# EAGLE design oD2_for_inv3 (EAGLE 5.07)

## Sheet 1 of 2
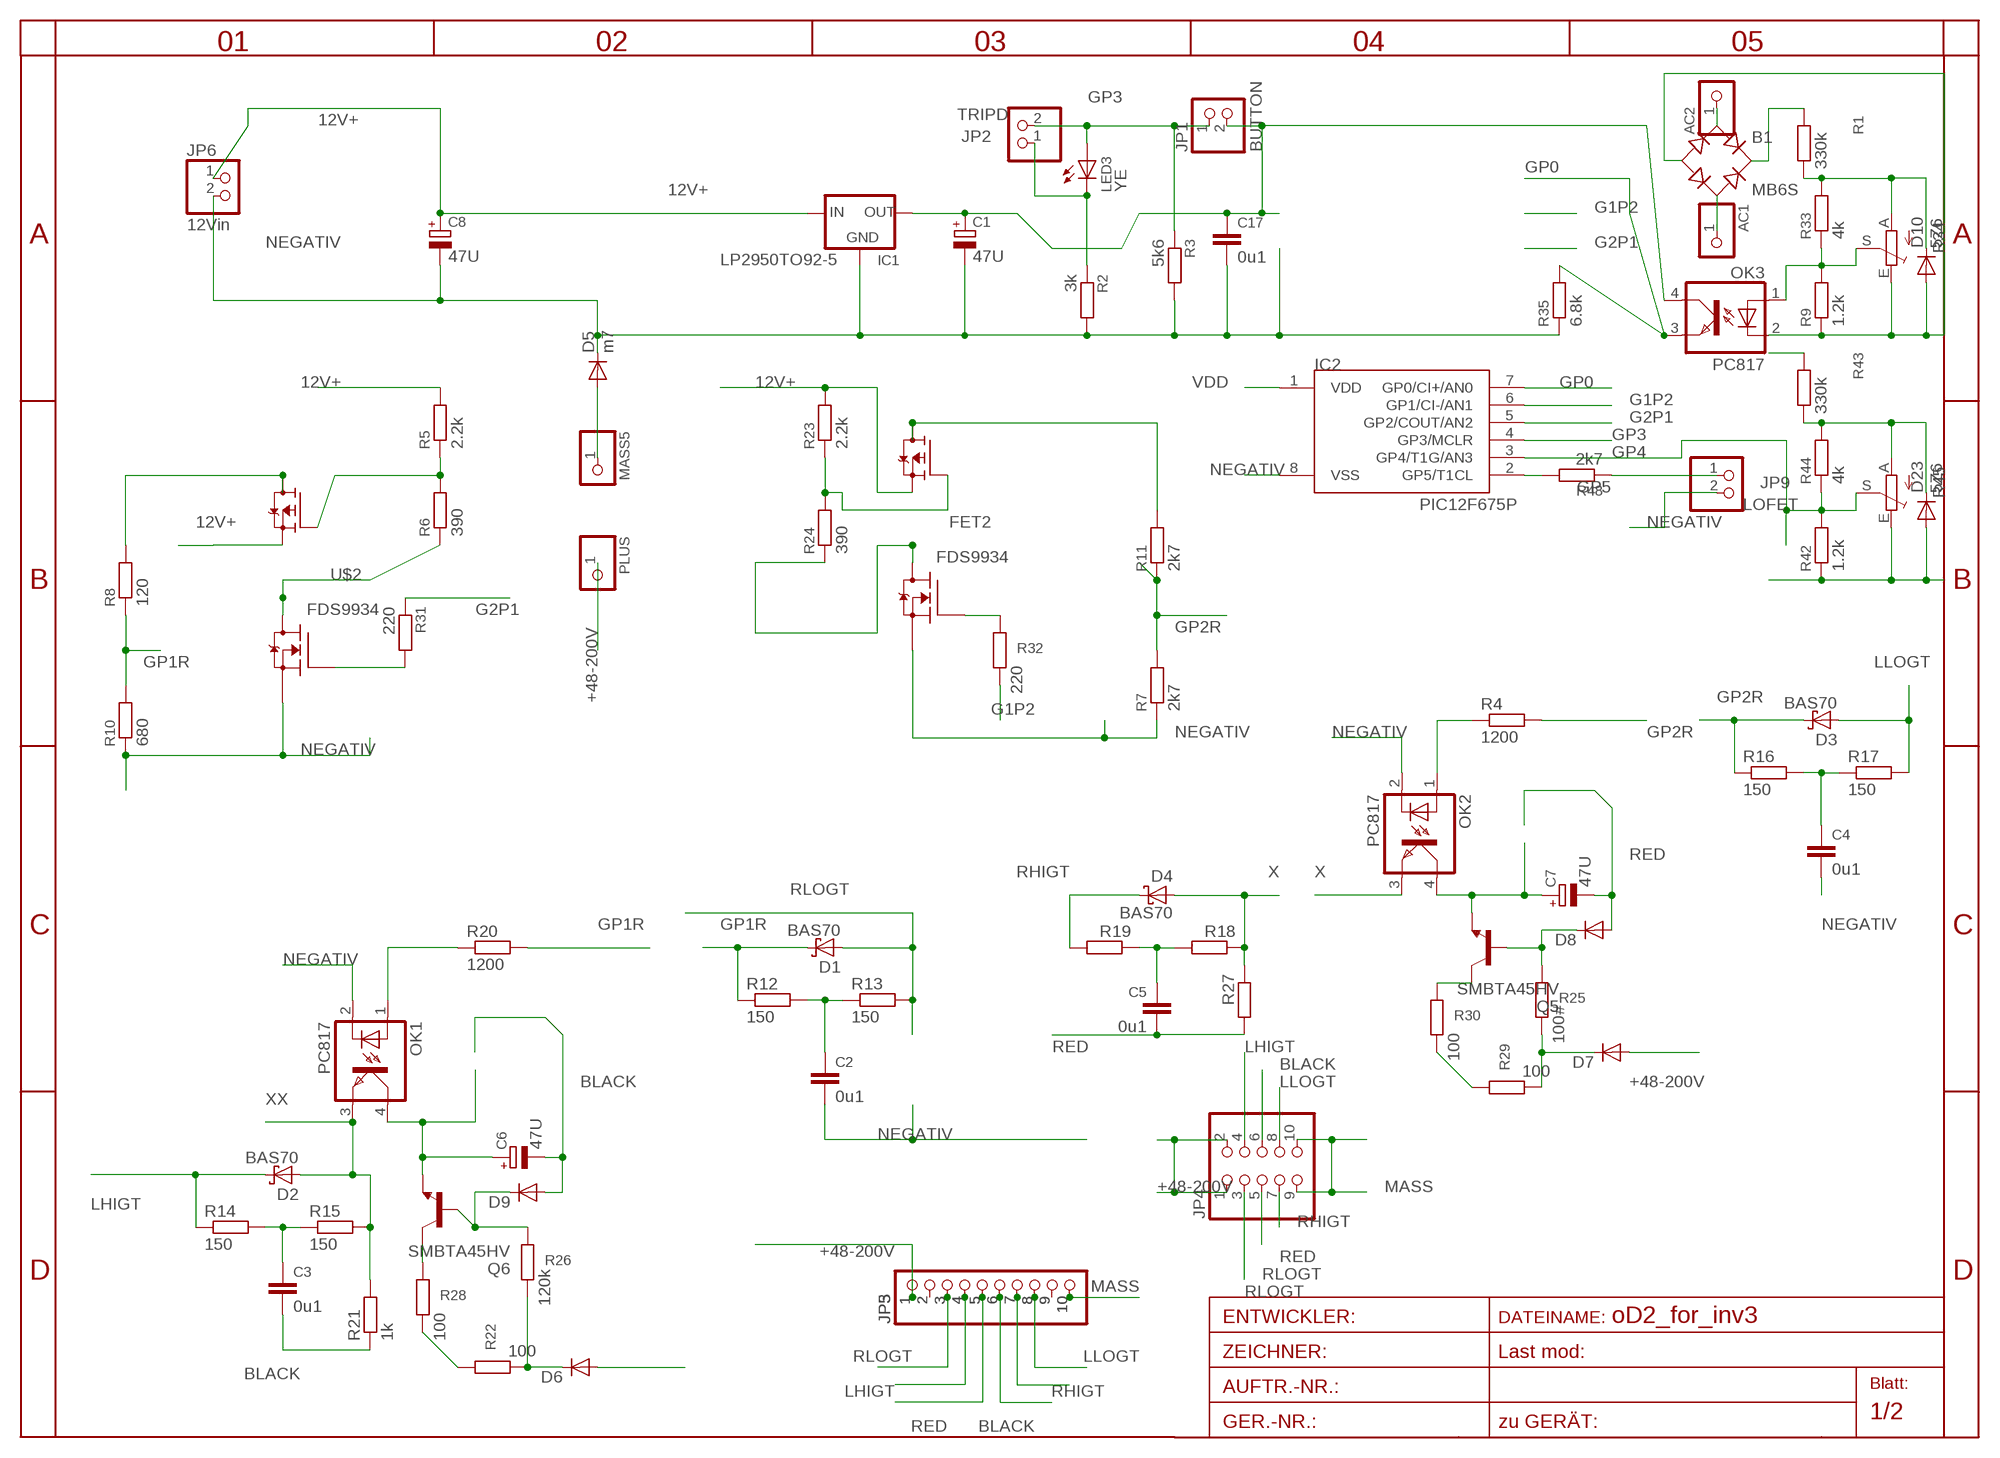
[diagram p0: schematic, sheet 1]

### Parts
AC1  PINHD-1X11MM6  [1X1MM8]
AC2  PINHD-1X11MM6  [1X1MM8]
B1  MB6S  [SOIC-4]
C1  47U  CPOL-EUE2.5-5  [E2,5-5]
C2  0u1  C-EUC1206  [C1206]
C3  0u1  C-EUC0805  [C0805]
C4  0u1  C-EUC1206  [C1206]
C5  0u1  C-EUC0805  [C0805]
C6  47U  CPOL-EUE2.5-6  [E2,5-6]
C7  47U  CPOL-EUE2.5-6  [E2,5-6]
C8  47U  CPOL-EUE2.5-7  [E2,5-7]
C17  0u1  C-EUC1206  [C1206]
D1  BAS70  [SOT23]
D2  BAS70  [SOT23]
D3  BAS70  [SOT23]
D4  BAS70  [SOT23]
D5  m7  DIODE-SMA-DO214  [SMA-DO214AC]
D6  DIODE-SMA-DO214  [SMA-DO214AC]
D7  DIODE-SMA-DO214  [SMA-DO214AC]
D8  DIODE-MINIMELF  [MINIMELF]
D9  DIODE-MINIMELF  [MINIMELF]
D10  5Z6  DIODE-MINIMELF  [MINIMELF]
D23  5Z6  DIODE-MINIMELF  [MINIMELF]
FET2  FDS9934  [SO-8]
IC1  LP2950TO92-5  [T092-5]
IC2  PIC12F675P  [DIL8]
JP1  BUTTON  PINHD-1X2STR  [1X02]
JP2  TRIPD  PINHD-1X2STR  [1X02]
JP3  PINHD-1X10  [1X10WIDE]
JP4  PINHD-2X5  [2X05]
JP5  PINHD-1X10  [1X10WIDE]
JP6  12Vin  PINHD-1X2STR  [1X02]
JP9  LOFET  PINHD-1X2STR  [1X02]
LED3  YE  LEDCHIPLED_1206  [CHIPLED_1206]
MASS5  PINHD-1X11MM6  [1X1MM8]
OK1  PC817  [DIL04]
OK2  PC817  [DIL04]
OK3  PC817  [DIL04]
PLUS  PINHD-1X11MM6  [1X1MM8]
Q5  SMBTA45HV  [SOT23HV]
Q6  SMBTA45HV  [SOT23HV]
R1  330k  R-EU_0204/5  [0204/5]
R2  3k  R-EU_R0805  [R0805]
R3  5k6  R-EU_R0805  [R0805]
R4  1200  R-EU_0204/7  [0204/7]
R5  2.2k  R-EU_R0805  [R0805]
R6  390  R-EU_R0805  [R0805]
R7  2k7  R-EU_R0805  [R0805]
R8  120  R-EU_R0805  [R0805]
R9  1.2k  R-EU_R0805  [R0805]
R10  680  R-EU_R0805  [R0805]
R11  2k7  R-EU_R0805  [R0805]
R12  150  R-EU_R0805  [R0805]
R13  150  R-EU_R0805  [R0805]
R14  150  R-EU_R0805  [R0805]
R15  150  R-EU_R0805  [R0805]
R16  150  R-EU_R0805  [R0805]
R17  150  R-EU_R0805  [R0805]
R18  R-EU_R0805  [R0805]
R19  R-EU_R0805  [R0805]
R20  1200  R-EU_0617/17  [0617/17]
R21  1k  R-EU_R0805  [R0805]
R22  100  R-EU_R1206  [R1206]
R23  2.2k  R-EU_R0805  [R0805]
R24  390  R-EU_R0805  [R0805]
R25  100#  R-EU_R1206  [R1206]
R26  120k  R-EU_R1206  [R1206]
R27  R-EU_R0805  [R0805]
R28  100  R-EU_R1206  [R1206]
R29  100  R-EU_R1206  [R1206]
R30  100  R-EU_R1206  [R1206]
R31  220  R-EU_R1206  [R1206]
R32  220  R-EU_R1206  [R1206]
R33  4k  R-EU_R0805  [R0805]
R34  TRIM_EU-S64W  [S64W]
R35  6.8k  R-EU_R0805  [R0805]
R42  1.2k  R-EU_R0805  [R0805]
R43  330k  R-EU_0207/50  [0207/50]
R44  4k  R-EU_R0805  [R0805]
R45  TRIM_EU-S64W  [S64W]
R48  2k7  R-EU_R0805  [R0805]
U$2  FDS9934  [SO-8]

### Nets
12V+: C8.+ FET2.3(Q2S) IC1.3(IN) JP6.1 R5.2 R23.2 U$2.3(Q2S)
+48-200V: D6.A D7.A JP3.1 JP4.1 JP4.2 JP5.1 PLUS.1 R43.2
BLACK: C3.2 C6.- D9.A JP3.6 JP4.6 JP5.6 R21.1
G1P2: IC2.6(GP1/CI-/AN1) R32.1
G2P1: IC2.5(GP2/COUT/AN2) R31.1
GP0: IC2.7(GP0/CI+/AN0) OK3.3(EMIT) R35.2
GP1R: D1.3(C) R8.1 R10.2 R12.1 R20.2
GP2R: D3.3(C) R4.2 R7.2 R11.1 R16.1
GP3: IC2.4(GP3/MCLR) JP1.1 JP2.2 LED3.A R3.1
GP4: IC2.3(GP4/T1G/AN3) R42.2 R44.1 R45.S
GP5: JP9.1 R48.1
LHIGT: D2.3(C) JP3.4 JP4.4 JP5.4 R14.1
LLOGT: D3.1(A) JP3.8 JP4.8 JP5.8 R17.2
MASS: D5.A JP3.10 JP4.9 JP4.10 JP5.10 MASS5.1 ; also sheet 2
N$2: FET2.2(Q1G) R32.2
N$3: C3.1 R14.2 R15.1
N$4: R5.1 R6.2 U$2.4(Q2G)
N$5: FET2.5(Q2D2) FET2.6(Q2D) R11.2
N$6: R31.2 U$2.2(Q1G)
N$7: C6.+ OK1.4(COL) Q6.2(E)
N$8: C5.1 R18.2 R19.1
N$9: FET2.7(Q1D2) FET2.8(Q1D1) R24.1
N$11: R6.1 U$2.7(Q1D2) U$2.8(Q1D1)
N$12: C2.1 R12.2 R13.1
N$13: OK2.1(A) R4.1
N$14: C7.+ OK2.4(COL) Q5.2(E)
N$15: JP2.1 LED3.C R2.1
N$16: C4.1 R16.2 R17.1
N$17: OK1.1(A) R20.1
N$20: D7.K(C) R25.1 R29.1
N$21: R8.2 U$2.5(Q2D2) U$2.6(Q2D)
N$22: FET2.4(Q2G) R23.1 R24.2
N$23: D6.K(C) R22.1 R26.1
N$24: Q6.3(C) R28.2
N$25: JP3.2 JP5.2
N$26: R22.2 R28.1
N$27: D9.C Q6.1(B) R26.2
N$28: R29.2 R30.1
N$31: D8.C Q5.1(B) R25.2
N$33: Q5.3(C) R30.2
N$34: JP3.9 JP5.9
N$35: OK3.1(A) R9.2 R33.1 R34.S
N$36: D10.C R1.1 R33.2 R34.A
N$37: B1.- D10.A OK3.2(C) R9.1 R34.E
N$38: AC1.1 B1.~2(AC2)
N$39: AC2.1 B1.~1(AC1)
N$40: B1.+ R1.2
N$41: D23.C R43.1 R44.2 R45.A
N$46: IC2.2(GP5/T1CL) R48.2
NEGATIV: C1.- C2.2 C4.2 C8.- C17.2 D5.K(C) D23.A FET2.1(Q1S) IC1.2(GND) IC2.8(VSS) JP6.2 JP9.2 OK1.2(C) OK2.2(C) R2.2 R3.2 R7.1 R10.1 R35.1 R42.1 R45.E U$2.1(Q1S)
RED: C5.2 C7.- D8.A JP3.5 JP4.5 JP5.5 R27.2
RHIGT: D4.3(C) JP3.7 JP4.7 JP5.7 R19.2
RLOGT: D1.1(A) JP3.3 JP4.3 JP5.3 R13.2
VDD: C1.+ C17.1 IC1.1(OUT) IC2.1(VDD) JP1.2 OK3.4(COL)
X: D4.1(A) OK2.3(EMIT) R18.1 R27.1
XX: D2.1(A) OK1.3(EMIT) R15.2 R21.2

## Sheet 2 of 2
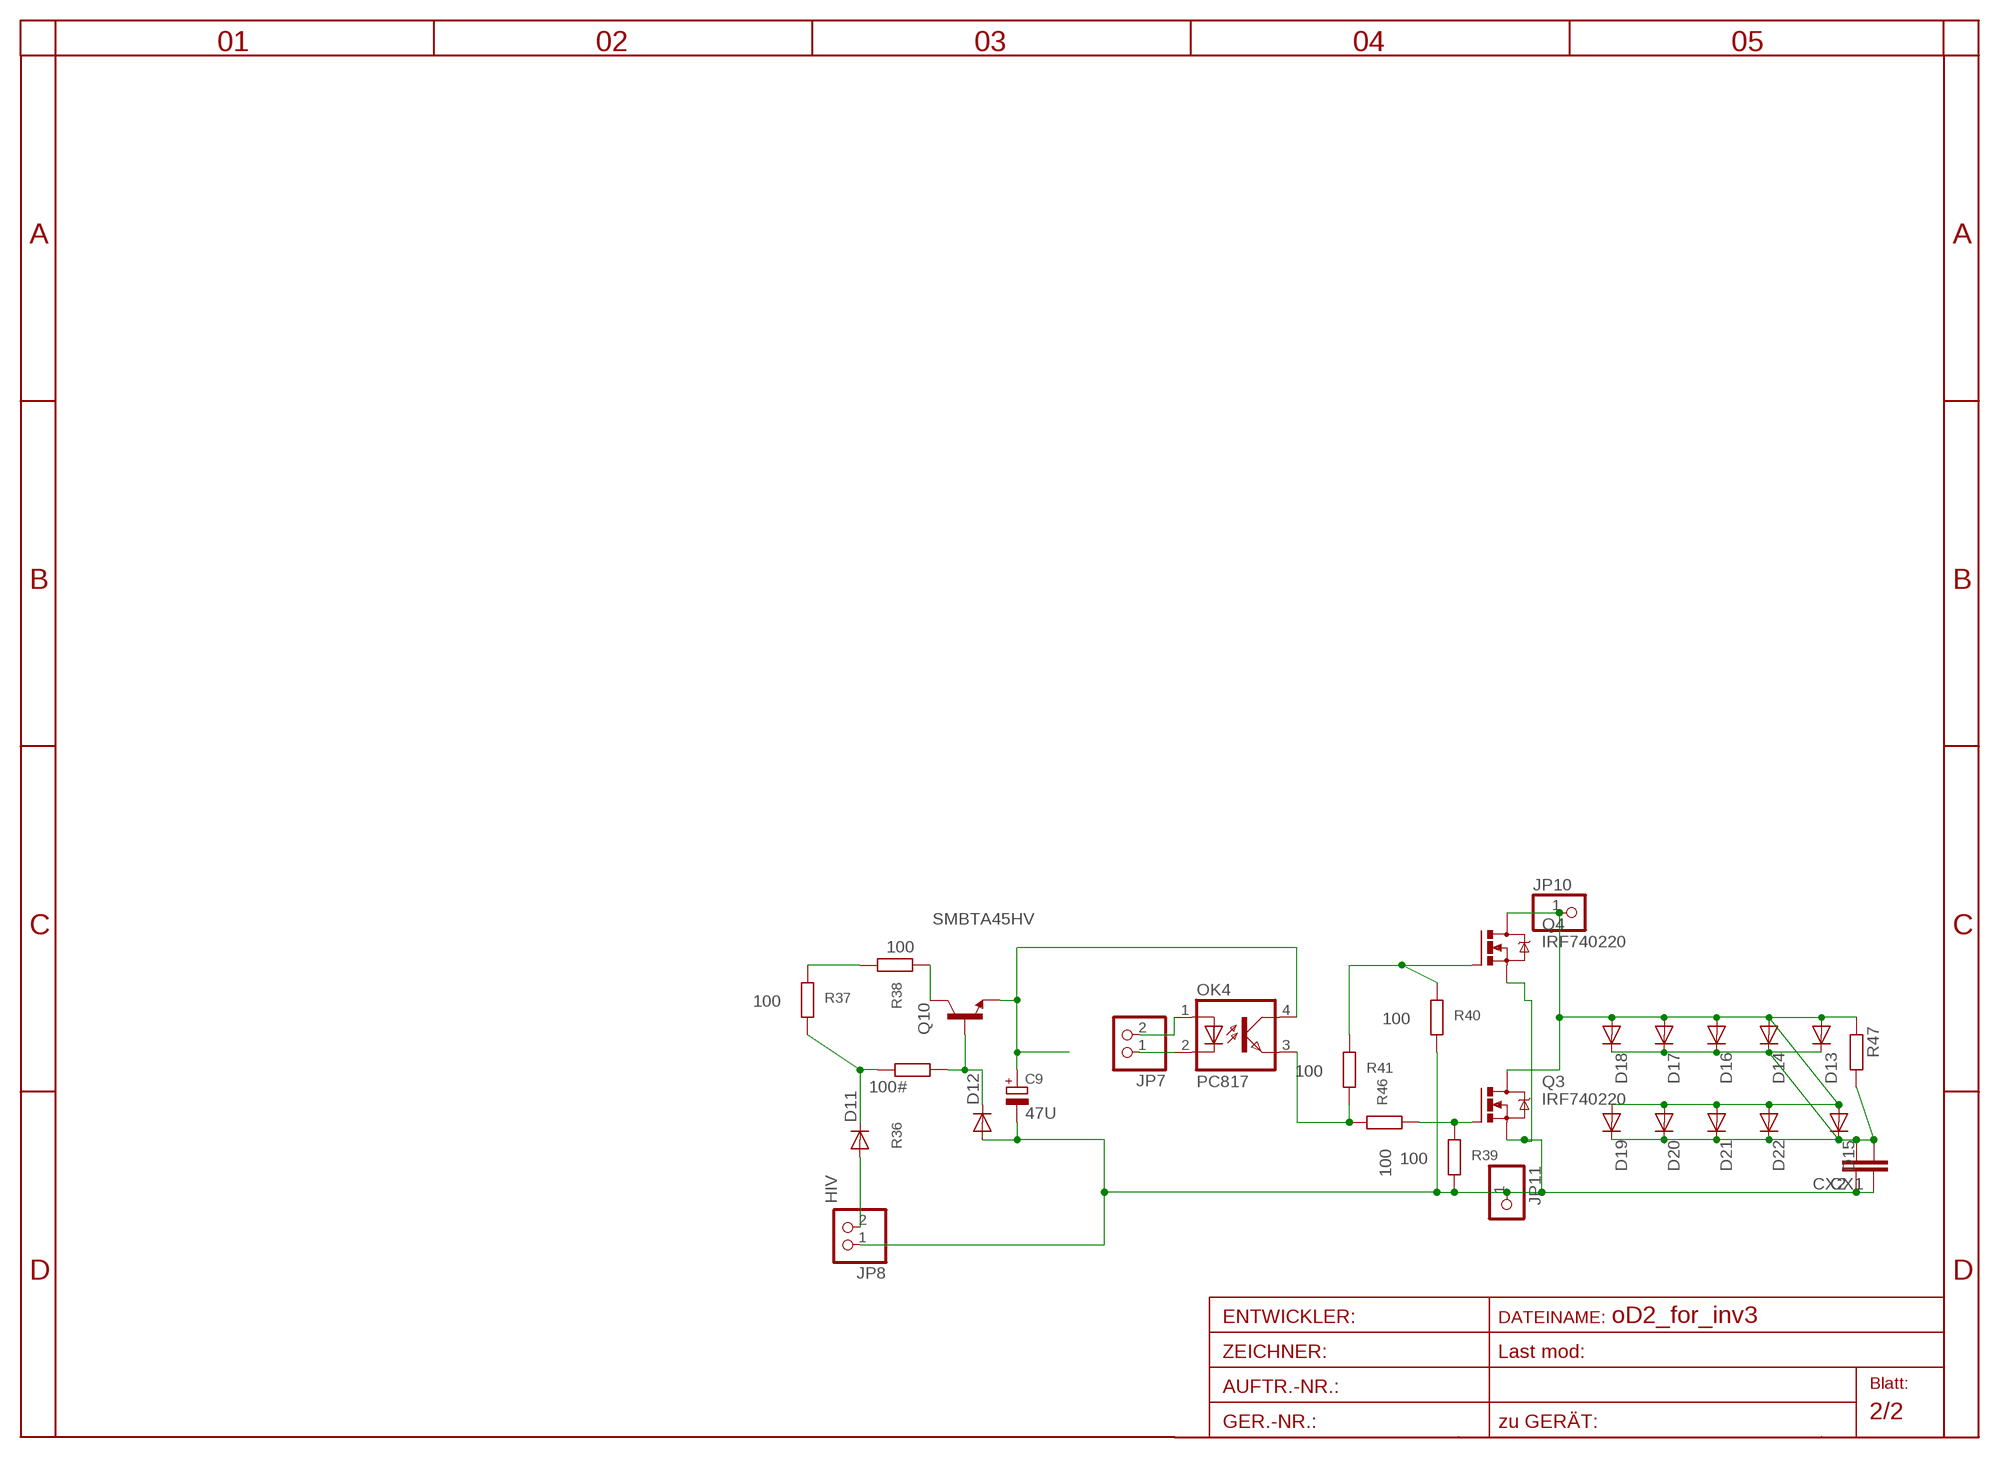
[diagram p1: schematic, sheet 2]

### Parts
C9  47U  CPOL-EUE2.5-6  [E2,5-6]
CX1  CXXC15B6  [XC15B6]
CX2  CXXC15B6  [XC15B6]
D11  DIODE-SMA-DO214  [SMA-DO214AC]
D12  DIODE-MINIMELF  [MINIMELF]
D13  DIODE-SMC  [SMC]
D14  DIODE-SMC  [SMC]
D15  DIODE-SMC  [SMC]
D16  DIODE-SMC  [SMC]
D17  DIODE-SMC  [SMC]
D18  DIODE-SMC  [SMC]
D19  DIODE-SMC  [SMC]
D20  DIODE-SMC  [SMC]
D21  DIODE-SMC  [SMC]
D22  DIODE-SMC  [SMC]
JP7  PINHD-1X2STR  [1X02]
JP8  PINHD-1X2STR  [1X02]
JP10  PINHD-1X14.5MM  [1X4MM5]
JP11  PINHD-1X14.5MM  [1X4MM5]
OK4  PC817  [DIL04]
Q3  IRF740220  [TO220BV]
Q4  IRF740220  [TO220BV]
Q10  SMBTA45HV  [SOT23HV]
R36  100#  R-EU_R1206  [R1206]
R37  100  R-EU_R1206  [R1206]
R38  100  R-EU_R1206  [R1206]
R39  100  R-EU_0204/7  [0204/7]
R40  100  R-EU_0204/7  [0204/7]
R41  100  R-EU_R1206  [R1206]
R46  100  R-EU_R1206  [R1206]
R47  R-EU_CERAM50  [CERAM50]

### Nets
BATT-: C9.- CX1.1 CX2.1 D12.A JP8.1 JP11.1 Q3.S Q4.S R39.1 R40.1
HIV: D11.A JP8.2
MASS: D13.A D14.A D15.A D16.A D17.A D18.A D19.A D20.A D21.A D22.A JP10.1 Q3.D Q4.D R47.1 ; also sheet 1
MX: CX1.2 CX2.2 D13.C D14.C D15.C D16.C D17.C D18.C D19.C D20.C D21.C D22.C R47.2
N$1: Q4.G R40.2 R41.2
N$42: JP7.1 OK4.2(C)
N$43: OK4.3(EMIT) R41.1 R46.2
N$44: JP7.2 OK4.1(A)
N$45: Q3.G R39.2 R46.1
N$48: C9.+ OK4.4(COL) Q10.2(E)
N$49: D11.K(C) R36.1 R37.1
N$50: R37.2 R38.1
N$51: D12.C Q10.1(B) R36.2
Q1: Q10.3(C) R38.2

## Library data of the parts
AC1 AC2 JP10 JP11 MASS5 PLUS = pinhead:PINHD-1X1: PIN HEADER
B1 = rectifier:MB*S: Bridge Rectifier Source: http://www.fairchildsemi.com/ds/MB/MB6S.pdf
C1 C6-C9 = rcl-2:CPOL-EU: POLARIZED CAPACITOR, European symbol
C2-C5 C17 = rcl-2:C-EU: CAPACITOR, European symbol
CX1 CX2 = rcl:CX: X CAPACITOR
D1-D4 = diode:BAS70: Silicon Schottky Diodes
D5-D23 = diode:DIODE-: DIODE
FET2 U$2 = transistor-fet:FDS9934
IC1 = v-reg:LP2950?*: Source: http://cache.national.com/ds/LP/LP2950.pdf
IC2 = microchip-3:PIC12F6*: uPC nW 1k Program Flash memory 2x Timer Comparator 10b A/D converter/ 4xIN
JP1 JP2 JP6-JP9 = pinhead:PINHD-1X2: PIN HEADER
JP3 JP5 = pinhead:PINHD-1X10: PIN HEADER
JP4 = pinhead:PINHD-2X5: PIN HEADER
LED3 = led:LED: LED
OK1-OK4 = optocoupler:PC817: SHARP OPTO COUPLER
Q3 Q4 = transistor-power:IRF740: N-CHANNEL MOS FET
Q5 Q6 Q10 = transistor-npn:SMBTA45
R1-R3 R5-R11 R22-R26 R28-R33 R35-R44 R46 R48 = rcl-2:R-EU_: RESISTOR, European symbol
R4 R12-R21 R27 R47 = rcl:R-EU_: RESISTOR, European symbol
R34 R45 = pot:TRIM_EU-: POTENTIOMETER

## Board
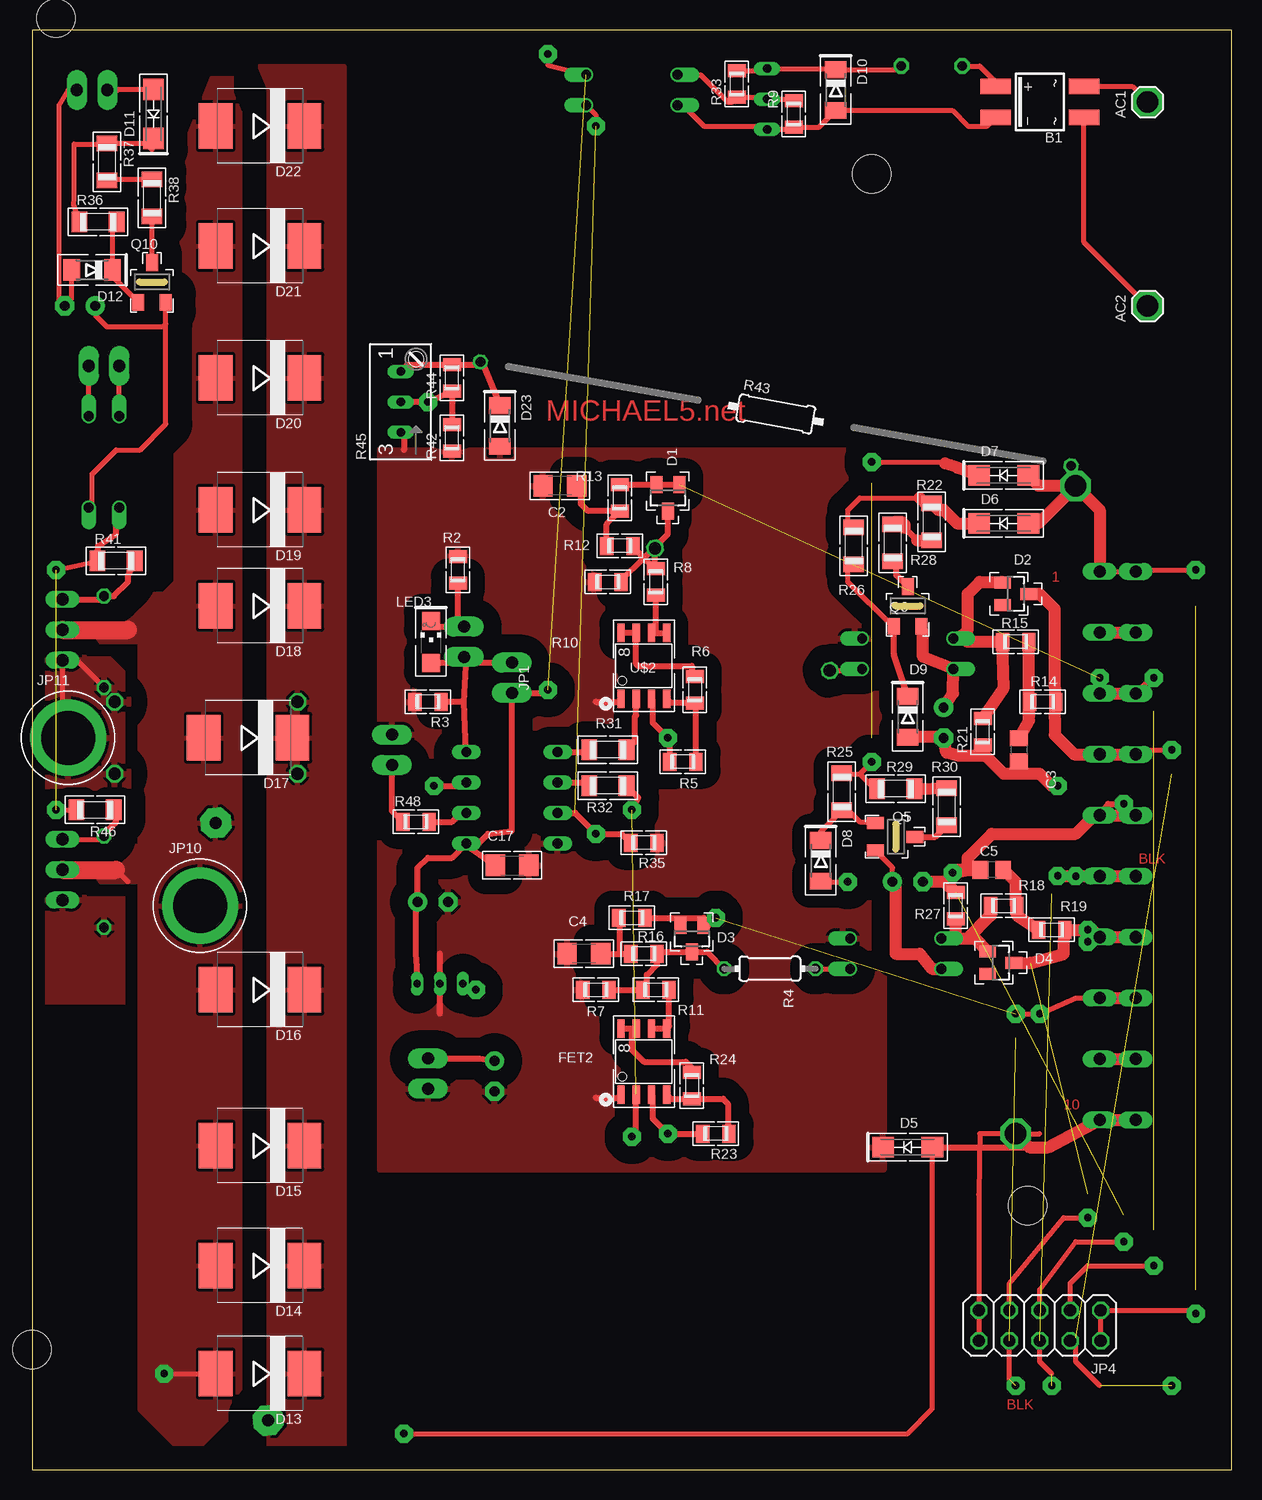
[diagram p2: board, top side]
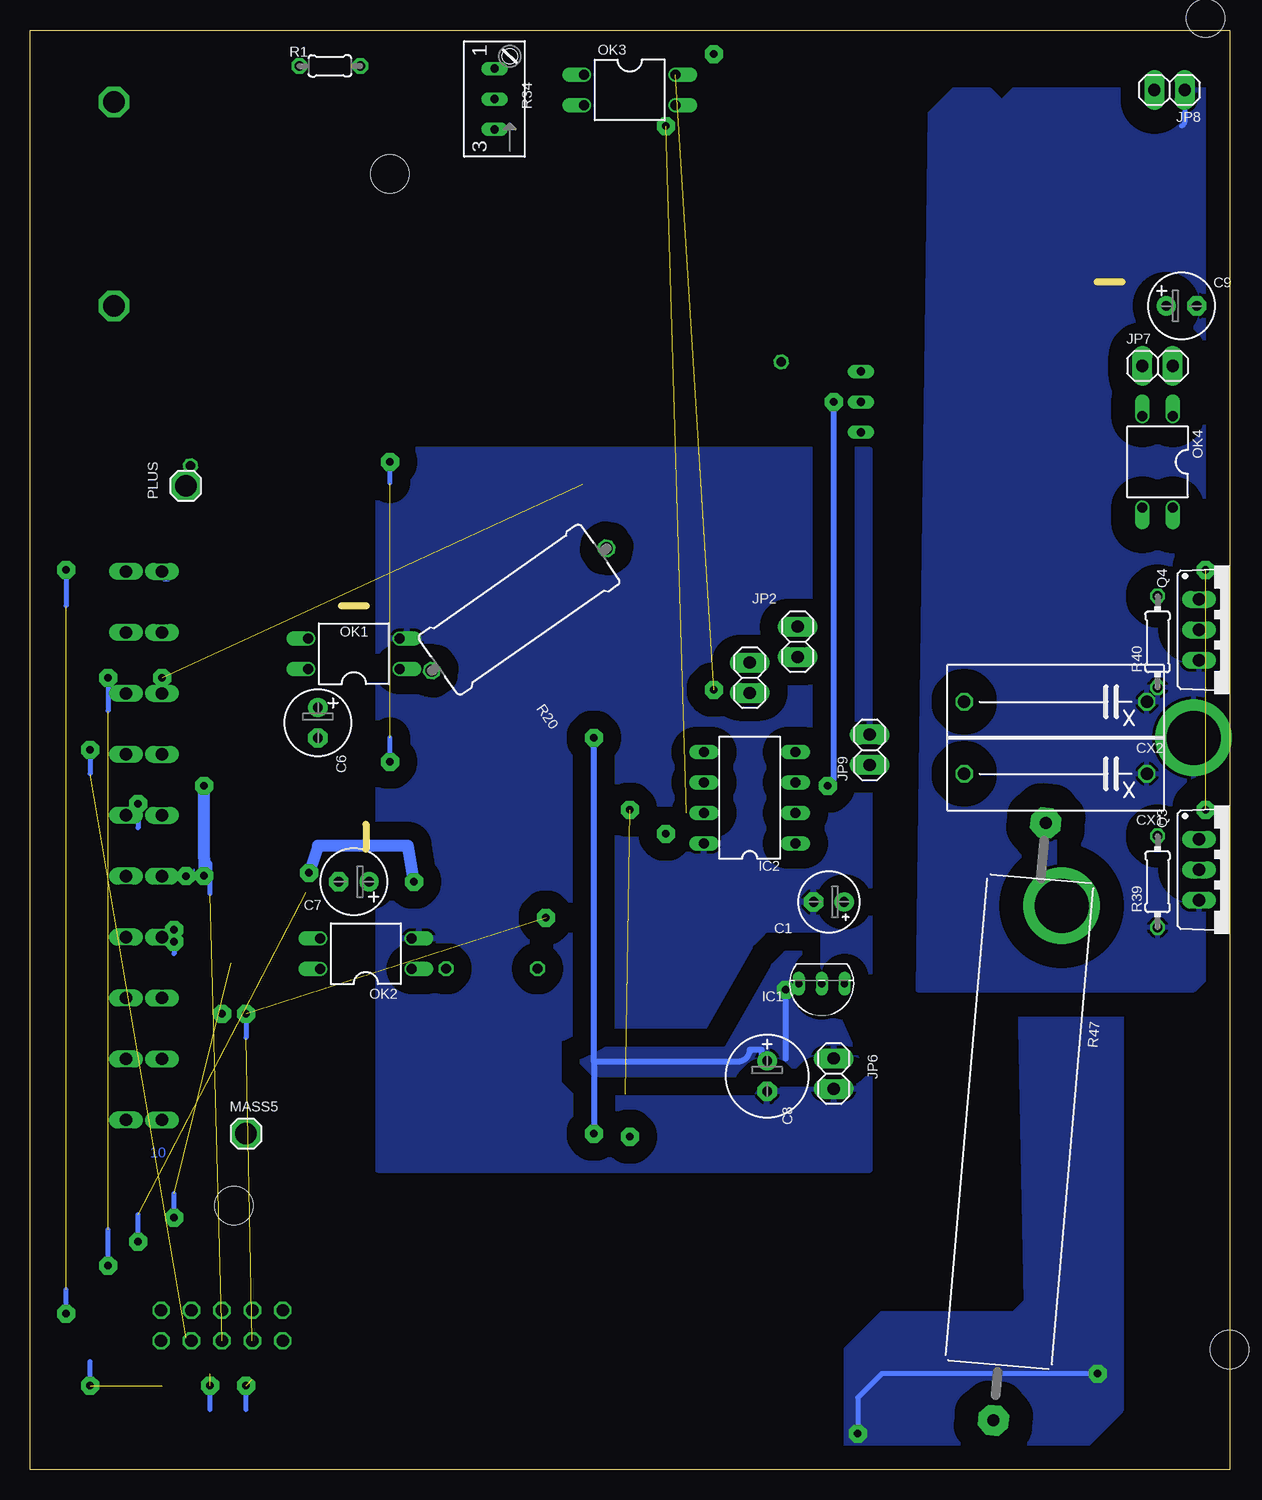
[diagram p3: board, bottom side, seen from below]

Size 100 x 120 mm. Coordinates in mm from the lower left corner, seen from the top.
Outline: 0,0 100,0 100,120 0,120 0,0
Copper layers (1*16): Top 0.035mm / dielectric 1.5mm / Bottom 0.035mm
Design rules "default *": minimum track width 12mil, minimum drill 24mil, track to track 8mil, track to pad 8mil, pad to pad 8mil, via to via 8mil, smd to smd 8mil, copper to edge 40mil, drill to drill 8mil, minimum pad ring 8mil, minimum via ring 8mil, stop-mask expansion 4mil, vias tented up to drill 0mil, thermal gap 10mil
Holes 3.2 mm at 2,121 0,10 70,108 83,22

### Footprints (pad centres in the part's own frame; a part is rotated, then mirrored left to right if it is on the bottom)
1X1MM8 = drill 1.8 pad 2.54 octagon: 1 0,0
SOIC-4 = smd 1.27 x 2.54: + 1.3,3.685; - -1.3,3.685; ~1 -1.3,-3.685; ~2 1.3,-3.685
E2,5-5 = drill 0.813 pad 1.6 round: + -1.27,0 | drill 0.813 pad 1.6 octagon: - 1.27,0
C1206 = smd 1.6 x 1.8: 1 -1.4,0; 2 1.4,0
C0805 = smd 1.3 x 1.5: 1 -0.95,0; 2 0.95,0
E2,5-6 = drill 0.813 pad 1.6 round: + -1.27,0 | drill 0.813 pad 1.6 octagon: - 1.27,0
E2,5-7 = drill 0.813 pad 1.6 round: + -1.27,0 | drill 0.813 pad 1.6 octagon: - 1.27,0
XC15B6 = drill 1.016 octagon: 1 -7.62,0; 2 7.62,0
SOT23 = smd 1 x 1.4: 1 -0.95,-1.1; 2 0.95,-1.1; 3 0,1.1
SMA-DO214AC = smd 1.8 x 1.7: A 2.05,-0.127; K -2.05,-0.127
MINIMELF = smd 1.4 x 1.8: A 1.7,0; C -1.7,0
SMC = smd 2.8 x 3.8: A 3.7,0; C -3.7,0
SO-8 = smd 1.524 x 0.61: 1 -2.743,1.905; 2 -2.743,0.635; 3 -2.743,-0.635; 4 -2.743,-1.905; 5 2.743,-1.905; 6 2.743,-0.635; 7 2.743,0.635; 8 2.743,1.905
T092-5 = drill 0.6 pad 0.813 long: 1 -1.905,0; 2 0,0; 3 1.905,0
DIL8 = drill 0.813 long: 1 -3.81,-3.81; 2 -1.27,-3.81; 3 1.27,-3.81; 4 3.81,-3.81; 5 3.81,3.81; 6 1.27,3.81; 7 -1.27,3.81; 8 -3.81,3.81
1X02 = drill 1.016 pad 1.676 long: 1 -1.27,0; 2 1.27,0
1X10WIDE = drill 1.016 long: 1 -22.86,0; 2 -17.78,0; 3 -12.7,0; 4 -7.62,0; 5 -2.54,0; 6 2.54,0; 7 7.62,0; 8 12.7,0; 9 17.78,0; 10 22.86,0
2X05 = drill 1.016 octagon: 1 -5.08,-1.27; 2 -5.08,1.27; 3 -2.54,-1.27; 4 -2.54,1.27; 5 0,-1.27; 6 0,1.27; 7 2.54,-1.27; 8 2.54,1.27; 9 5.08,-1.27; 10 5.08,1.27
1X4MM5 = drill 4.5 pad 6.35 round: 1 0,0
CHIPLED_1206 = smd 1.5 x 1.5: A 0,-1.75; C 0,1.75
DIL04 = drill 0.813 offset: 1 -1.27,-3.81; 2 1.27,-3.81; 3 1.27,3.81; 4 -1.27,3.81
TO220BV = drill 1.016 long: D 0,-2.54; G -2.54,-2.54; S 2.54,-2.54
SOT23HV = smd 1 x 1.4: 1 -1.15,-1.7; 2 1.15,-1.7; 3 0,1.6
0204/5 = drill 0.8 pad 1.27 octagon: 1 -2.54,0; 2 2.54,0
R0805 = smd 1.1 x 1.5: 1 -1.1,0; 2 1.1,0
0204/7 = drill 0.813 octagon: 1 -3.81,0; 2 3.81,0
0617/17 = drill 1.016 octagon: 1 -8.89,0; 2 8.89,0
R1206 = smd 1.3 x 1.7: 1 -1.55,0; 2 1.55,0
S64W = drill 0.7 long: A 2.54,1.27; E -2.54,1.27; S 0,1.27
0207/50 = drill 0.813 octagon: 1 -25,0; 2 25,0
CERAM50 = drill 1 pad 2.54 octagon: 1 -25,0; 2 25,0

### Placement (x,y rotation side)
AC1  93,114 90 top
AC2  93,97 90 top
B1  84,114 90 top
C1  33.4,47.32 180 bottom
C2  44,82 180 top
C3  82.25,60 270 top
C4  46,43 180 top
C5  80,50 180 top
C6  76,62.25 270 bottom
C7  73,49 180 bottom
C8  38.55,32.8 270 bottom
C9  4,97 0 bottom
C17  40.01,50.37 0 top
CX1  14.5,58 180 bottom
CX2  14.5,64 180 bottom
D1  53,81 180 top
D2  82,73 270 top
D3  55,44.25 180 top
D4  80.75,42.25 270 top
D5  73,27 0 top
D6  81,79 0 top
D7  81,83 0 top
D8  65.75,50.75 270 top
D9  73,62.75 270 top
D10  67,115 270 top
D11  10,113 90 top
D12  5,100 180 top
D13  19,8 180 top
D14  19,17 180 top
D15  19,27 180 top
D16  19,40 180 top
D17  18,61 180 top
D18  19,72 180 top
D19  19,80 180 top
D20  19,91 180 top
D21  19,102 180 top
D22  19,112 180 top
D23  39,87 270 top
FET2  51,34 90 top
IC1  34,40.5 180 bottom
IC2  40,56 90 bottom
JP1  40,66 270 bottom
JP2  36,69 270 bottom
JP3  89,52 270 bottom
JP4  84,12 180 top
JP5  92,52 270 top
JP6  33,33 270 bottom
JP7  6,92 0 bottom
JP8  5,115 180 bottom
JP9  30,60 90 bottom
JP10  14,47 0 top
JP11  3,61 0 top
LED3  33.25,69 0 top
MASS5  82,28 0 bottom
OK1  73,68 90 bottom
OK2  72,43 90 bottom
OK3  50,115 270 bottom
OK4  6,84 180 bottom
PLUS  87,82 180 bottom
Q3  0,50 270 bottom
Q4  0,70 270 bottom
Q5  72,52.75 270 top
Q6  73,72 0 top
Q10  10,99 0 top
R1  75,117 180 bottom
R2  35.5,75 90 top
R3  33,64 180 top
R4  61.5,41.75 180 top
R5  54.25,59 180 top
R6  55.25,65 270 top
R7  47,40 0 top
R8  52,74 270 top
R9  63.5,113 90 top
R10  48,74 0 top
R11  52,40 0 top
R12  49,77 180 top
R13  49,81 90 top
R14  84.25,64 180 top
R15  82,69 180 top
R16  51,43 180 top
R17  50,46 0 top
R18  81,47 0 top
R19  85,45 0 top
R20  59.22,71.69 35 bottom
R21  79.25,61.5 90 top
R22  75,79 270 top
R23  57,28 180 top
R24  55,32 270 top
R25  67.5,56.5 270 top
R26  68.5,77 270 top
R27  77,47 90 top
R28  71.75,77.25 270 top
R29  72,56.75 0 top
R30  76.25,55.25 270 top
R31  48,60 0 top
R32  48,57 0 top
R33  58.75,115.5 90 top
R34  60,114.25 90 bottom
R35  51,52.25 180 top
R36  5.5,104 0 top
R37  6.25,109 270 top
R38  10,106 270 top
R39  6,49 90 bottom
R40  6,69 90 bottom
R41  7,75.75 0 top
R42  35,86 90 top
R43  62,88 350 top
R44  35,91 90 top
R45  32,89 90 top
R46  5.25,55 180 top
R47  17.5,29 265 bottom
R48  32,54 0 top
U$2  51,67 90 top

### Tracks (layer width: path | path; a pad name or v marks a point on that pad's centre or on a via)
12V+  (via drill 0.6 pad 1.5)
  Top 0.5: JP6.1 37.34,34.27 C8.+ | R23.2 v53,28 53,28.5 52.5,28.5 51.75,29.25 51.75,31.14 FET2.3 | R5.2 53.15,60.85 v53,61 51.75,62.25 51.75,64.14 U$2.3 | IC1.3 36.41,40 v37,40
  Bottom 0.5: 53,34 v53,28 | 53,34 v53,61 | 37,34.27 v37,40 | C8.+ arc90 39,34.52 39,35 40,35 arc90 41,34 53,34
  pour Bottom (isolate 2, rank 2): 35,43 37,43 38,42 42,35 52,35 54,34 53,33 32,33 31,34
+48-200V  (via drill 0.6 pad 1.5)  (1 unrouted)
  Top 0.406: JP4.2 JP4.1 96.73,13.27 v97,13 | JP3.1 JP5.1 92.14,75 v97,75 | PLUS.1 87,83.28 R43.2
  Top 1: JP3.1 89,80 PLUS.1 | PLUS.1 83.92,82 D7.A | D6.A 83.87,78.87 PLUS.1
  Bottom 0.406: v97,13 97,15 | v97,75 97,72
BATT-
  Top 0.406: D12.A 3.3,97.57 C9.- 2.25,97.48 2.25,113.75 3,115 JP8.1 | JP11.1 2.54,61.46 Q4.S 3.73,67.46 R40.1
  Bottom 0.406: JP8.1 3.73,112.27 4,112
  pour Top (isolate 1.016, rank 3): 1,68 6,68 8,66 8,39 1,39
  pour Bottom (isolate 2, rank 2): 1,115 18,115 19,114 20,115 23,115 25,113 26,40 3,40 0,43
BLACK  (via drill 0.6 pad 1.5)  (2 unrouted)
  Top 0.406: 79,59.5 R21.1 | JP4.6 84,9 85,8
  Top 1: v85.5,49.5 86.29,49.46 v87,49.46 JP3.6 JP5.6 | v85.5,57 85,57 84,58 82,58 | C6.- 76.23,59.77 77.25,59.5 79,59.5 79.5,59.5 81,58 82,58 | C3.2 82.25,58.25 82,58
  Top 1.016: D9.A 75.68,61.05 C6.-
  Bottom 0.406: 85,5 v85,7 | 85.5,51 85,50.5 85,48
  Bottom 1: v85.5,57 85.5,51 v85.5,49.5
G1P2
  Top 0.5: IC2.6 46.18,57.27 R32.1
G2P1
  Top 0.5: IC2.5 46.26,59.81 R31.1
GP0  (via drill 0.6 pad 1.5)  (1 unrouted)
  Top 0.406: v47,112 47,112.92 OK3.3
  Top 0.5: IC2.7 45.27,54.73 v47,53 49.15,53 R35.2
GP1R
  Top 0.5: R10.2 49.1,74.1 51,76 | 51,76 53,78 D1.3 | R12.1 50.1,76.9 51,76 | 51,76 51.9,75.1 R8.1 51.93,75.17 R20.2
GP2R
  Top 0.5: R7.2 R11.1 51.25,40.35 51.25,41.25 52.1,42.1 R16.1 52.25,43.15 D3.3 56.29,43.15 R4.2
GP3
  Top 0.5: IC2.4 36,64 | 36,64 36.19,67 | 36.19,67 36.19,67.54 JP2.2 36.46,67.27 JP1.1 | 36,64 R3.1 | LED3.A 35.94,67.25 36.19,67
GP4  (via drill 0.6 pad 1.5)
  Top 0.5: IC2.3 35.92,57 v33.5,57 | R42.2 R44.1 v33,89 R45.S
  Bottom 0.5: v33.5,57 33,57.5 v33,89
GP5
  Top 0.5: JP9.1 30,54.9 R48.1
HIV
  Top 0.406: D11.A 7.22,115.05 7.17,115 JP8.2
LHIGT  (via drill 0.6 pad 1.5)  (2 unrouted)
  Top 0.406: JP4.4 86.73,10.73 87,11 87,9 89,7 | JP5.4 92.38,60 v95,60
  Top 1: D2.3 84,73 85.25,71.75 85.25,65.5 85.35,64.4 R14.1 85.25,62.65 85.25,61.25 86.88,59.62 JP3.4 JP5.4
  Bottom 0.406: v95,7 95,9 | v95,60 95,58
LLOGT  (via drill 0.6 pad 1.5)  (3 unrouted)
  Top 0.406: JP3.8 87,39.3 v84,38 v82,38 | 81.46,7.54 JP4.8
  Top 0.5: R17.2 56,46 55.95,45.95 D3.1 56.35,45.35 v57,46
  Top 1: JP3.8 JP5.8
  Bottom 0.406: 82,5 v82,7 | v82,38 82,36
MASS  (via drill 0.6 pad 1.5)
  Top 0.406: 84,28 MASS5.1 79,28 78.92,22.92 JP4.9 JP4.10 | D5.A 75.05,5.05 73,3 v31,3 | 7,50 8,49 | v11,8 D13.A
  Top 0.5: D5.A 83.13,26.87
  Top 1: MASS5.1 83.13,26.87 84.73,26.87 JP3.10 JP5.10
  Top 1.5: Q4.D 8,70 | Q3.D 7,50
  Bottom 0.406: v31,3 31,6 29,8 v11,8
  pour Top (isolate 2, rank 2): 15,116 17,116 19,114 19,7 14,2 12,2 9,5 9,49 2,49 2,52 9,52 9,69 1,69 1,72 2,73 11,73 12,74 12,110 13,111
  pour Bottom (isolate 2, rank 4): 15,116 17,116 19,114 17,14 18,13 29,13 32,10 32,2 12,2 9,5 9,42 2,49 2,52 8,52 13,57 13,65 11,67 3,67 1,69 1,72 2,73 11,73 12,74 12,110 13,111
MX
  pour Top (isolate 2): 19,117 26,117 26,2 20,2 19.75,2 19.75,115.25
N$1
  Top 0.5: Q4.G 5.73,72.54 R40.2 6.81,72.81 8,74 8,74.55 R41.2
N$2  (via drill 0.6 pad 1.5)  (1 unrouted)
  Top 0.5: R32.2 50.55,56 v50,55 | v50,27.75 50.37,27.64 FET2.2
N$3
  Top 1: R15.1 83.1,62.8 R14.2 83.1,62.45 C3.1
N$4
  Top 0.5: U$2.4 53.26,63.9 R6.2 55.35,63.8 R5.1
N$5
  Top 0.5: FET2.6 FET2.5 53.1,36.94 R11.2
N$6
  Top 0.5: R31.2 50.25,60.7 50.25,62.75 50.37,62.87 U$2.2
N$7
  Top 0.5: Q6.2 74.15,69.95 74.25,69.85
  Top 1: 74.25,69.85 74.25,68.5 74.27,67.73 OK1.4 76.77,64.69 C6.+
N$8
  Top 1: R19.1 82.1,46.2 R18.2 82,47.1 82,49 81,50 C5.1
N$9
  Top 0.5: FET2.8 FET2.7 50,36.38 50,35 51,34 54.5,34 55,33.5 R24.1
N$11
  Top 0.5: R6.1 55,66.35 55,67 50.5,67 50.37,67.14 U$2.7 U$2.8
N$12
  Top 0.5: R12.2 47.9,78.8 R13.1 46.35,79.9 45.75,80.5 45.75,81.65 C2.1
N$13
  Top 0.406: R4.1 68.17,41.75 OK2.1
N$14
  Top 0.406: Q5.2 71.73,50.17 C7.+ 72,48.73
  Top 1: OK2.4 75.02,41.73 74,43 72,43 72,48.73
N$15
  Top 0.5: LED3.C 33.73,70.27 JP2.1 35.5,70.77 R2.1
N$16
  Top 0.5: C4.1 49,43 | 49,43 R16.2 | R17.1 49,45.9 49,43
N$17
  Top 0.406: R20.1 69.05,66.59 OK1.1
N$20  (via drill 0.6 pad 1.5)  (1 unrouted)
  Top 0.406: R29.1 70.25,56.75 69,58 | 69,58 67.55,58 R25.1 | 69,58 v70,59 | v70,84 76.68,84 77.18,83.5
  Top 0.5: 76.13,83.87 76,84
  Top 1: 76.13,83.87 77.18,83.5 D7.K
  Bottom 0.406: v70,59 70,61 | 70,82.25 v70,84
N$21
  Top 0.5: U$2.5 U$2.6 51.74,69.74 52,70 R8.2
N$22
  Top 0.5: FET2.4 53.26,30.9 R24.2 57.6,30.9 58,30.5 58,28.1 R23.1
N$23
  Top 0.406: 74,81 69,81 68,80 68,79.05 R26.1
  Top 1: 74,81 74.45,80.55 R22.1 75.55,80 76,80 77.13,78.87 D6.K
N$24
  Top 0.5: 72.05,75.7 72.05,74.55 Q6.3
  Top 1: 72.05,75.7 R28.2
N$25
  Top 1.016: JP3.2 JP5.2
N$26
  Top 0.5: 72.75,78.5 73.8,77.45 | 72.75,78.75 72.5,79
  Top 1: 73.8,77.45 R22.2 | 72.75,78.5 72.75,78.75 | 72.5,79 71.95,79 R28.1
N$27
  Top 0.406: 71.7,70.3 68,74 68,74.95 R26.2
  Top 0.5: D9.C 71.85,67.95 Q6.1 71.7,70.3
N$28
  Top 1: R29.2 73.7,56.75 R30.1
N$31
  Top 0.406: D8.C 65.75,53.2 R25.2 68.05,54.95 69,54 70.2,54 Q5.1
N$33
  Top 0.5: Q5.3 75.3,52.75 R30.2
N$34
  Top 1: JP3.9 JP5.9
N$35
  Top 0.406: OK3.1 55.73,116.27 58,114 58.35,114 R33.1 61.12,114.4 R34.S 63.35,114.25 R9.2
N$36
  Top 0.406: R33.2 61.08,116.6 R34.A 66.91,116.79 D10.C 72.16,116.7 R1.1
N$37
  Top 0.406: OK3.2 54.27,113.73 56,112 60.98,112 R34.E 63.31,111.71 R9.1 65.6,111.9 D10.A 76.7,113.3 78,112 79.61,112 B1.-
N$38
  Top 0.406: B1.~2 91.7,115.3 AC1.1
N$39
  Top 0.406: B1.~1 87.69,102.31 AC2.1
N$40
  Top 0.406: B1.+ 80.31,115.69 79,117 R1.2
N$41
  Top 0.5: 37.6,92.1 D23.C | 37.6,92.1 R44.2 31.29,92.1 R45.A | 37.6,92.1 37.6,92.12 R43.1
N$42
  Top 0.406: OK4.2 JP7.1
N$43  (via drill 0.6 pad 1.5)  (1 unrouted)
  Top 0.406: v2,55 R46.2 | v2,75 R41.1
  Top 0.5: R41.1 5.45,76.45 5.5,77 7,78 7,79.92 OK4.3
N$44
  Top 0.406: OK4.1 JP7.2
N$45
  Top 0.406: Q3.G 5.73,52.54 R39.2
  Top 0.5: R39.2 6,53 7,54 7,54.8 R46.1
N$46
  Top 0.5: R48.2 35,54 36,55 36,54.92 IC2.2
N$48
  Top 0.406: 11.15,95.5 11.15,87.15 9,85 7,85 5,83 5,80.46 OK4.4 | 11.15,95.5 Q10.2 | C9.+ 5.27,96.23 6.25,95.25 10.9,95.25 11.15,95.5
N$49
  Top 0.406: R36.1 3.45,105.45 3.5,106 3.5,110.5 6.45,110.5 R37.1 9.45,110.55 10,110 10,110.82 D11.K
N$50
  Top 0.406: R38.1 7.1,107.55 R37.2
N$51
  Top 0.406: Q10.1 6.7,99.45 D12.C 6.7,103.15 R36.2
NEGATIV
  Top 0.5: R45.E 31,86.19 31,85 | U$2.1 48.84,64 47,64 | FET2.1 48.84,31 47,31 | 34,43 IC1.2 34,38
  pour Top (isolate 1.5, rank 4): 29,85 71,85 71,25 29,25
  pour Bottom (isolate 1.5, rank 3): 30,85 71,85 71,25 30,25
Q1
  Top 0.406: Q10.3 R38.2
RED  (via drill 0.6 pad 1.5)  (1 unrouted)
  Top 0.406: v68,49 65.8,49 D8.A | JP4.5 84,15 87,19 v91,19 | JP5.5 92.46,55
  Top 0.5: v91,55.5 89.71,55.5 JP3.5
  Top 1: 76.1,49 C7.- | 76.1,49 R27.2 | 78,50 77.1,50 76.1,49 | 78,50 C5.2 | 78,50 78,51 80,53 87,53 88.54,54.54 JP3.5 JP5.5 | v76.75,49.75 78,50
  Bottom 0.406: v91,55.5 91,53.5 | v91,19 91,21.25
  Bottom 1: v68,49 68.5,52 76,52 v76.75,49.75
RHIGT  (via drill 0.6 pad 1.5)  (1 unrouted)
  Top 0.406: JP4.7 81.46,15.46 86,21 v88,21 | JP5.7 92.38,44 | v88,45 v88,44
  Top 1: D4.3 83.25,42.25 86,43 86,43.9 R19.2 | JP3.7 JP5.7
  Top 1.016: R19.2 v88,45 88.38,45 JP3.7
  Bottom 0.406: v88,44 88,43 | v88,21 88,23
RLOGT  (via drill 0.6 pad 1.5)  (2 unrouted)
  Top 0.406: JP4.3 86.54,15.54 88,17 v93.5,17 | 93,65 92.3,65 JP5.3 93,65.7 v93.5,66
  Top 0.5: R13.2 D1.1
  Top 1: v89,66 JP3.3 JP5.3
  Bottom 0.406: v93.5,17 93.5,20 | v93.5,66 93.5,63.25
VDD  (via drill 0.6 pad 1.5)  (1 unrouted)
  Top 0.406: v43,118 43,117.08 OK3.4
  Top 0.5: JP1.2 40,64.98 | JP1.2 40,53.25 38,53 37,52 36.38,52 IC2.1 | C17.1 36.61,51.77 IC2.1 | IC2.1 35,51 33,51 32.13,50.13 C1.+ 32,47.19 32,43 32.09,41.91 IC1.1 | JP1.2 42.73,64.73 v43,65
X
  Top 1: OK2.3 77,44.27 | 77,44.27 78,44.27 | 78,44.27 78.58,44.27 D4.1 | R18.1 79.9,46.17 78,44.27 | 77,44.27 R27.1
XX
  Top 1: OK1.3 77.27,69.27 77.5,69.5 | 77.5,69.5 78,70 78,73 79,74 80.85,74 D2.1 | 77.5,69.5 78,69 R15.2 81,65.15 R21.2

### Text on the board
Top: MICHAEL5.net | 1 | BLK | 10 | BLK
Bottom: 1 | BLK | 10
